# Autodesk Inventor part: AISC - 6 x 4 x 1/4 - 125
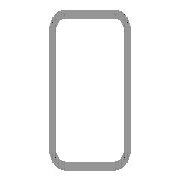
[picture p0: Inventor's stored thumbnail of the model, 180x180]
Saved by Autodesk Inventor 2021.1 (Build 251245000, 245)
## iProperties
Created: 2018-01
Part Number: AISC - 6 x 4 x 1/4 - 125
Material: Steel, Galvanized
Description: Tube
Document SubType Name: Modeling
Standard: AISC
Designer: u1426
Standards Organization: ANSI
Language: en-US
Size Designation: 6 x 4 x 1/4 - 125
Categories: <MemberInstance><Categories><Category DisplayName="Structural Shapes" InternalName="089c4875-fa83-4c05-b084-43b9cc11f5ed" Mnemonic="GRDR"><CategoryParameter Dis
Stock Number: 6 x 4 x 1/4
Density: 7.85 g/cm^3
Appearance: Galvanized
IsCustomPart: 1
G_L: 125.000 in
Author: u1426
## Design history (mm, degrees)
node "Start plane"
sketch "Sketch"
  geometry: L1 (-50.8, -63.5)-(-50.8, 63.5); L2 (-38.1, 76.2)-(38.1, 76.2); L3 (50.8, 63.5)-(50.8, -63.5); L4 (38.1, -76.2)-(-38.1, -76.2); L5 (-38.1, 69.85)-(38.1, 69.85); L6 (44.45, 63.5)-(44.45, -63.5); L7 (38.1, -69.85)-(-38.1, -69.85); L8 (-44.45, -63.5)-(-44.45, 63.5); L9 (0, 110.362)-(0, -110.362) reference; L10 (-74.802, 0)-(74.802, 0) reference; A1 r 12.7 centre (-38.1, -63.5) between (-50.8, -63.5) and (-38.1, -76.2); A2 r 12.7 centre (-38.1, 63.5) between (-38.1, 76.2) and (-50.8, 63.5); A3 r 12.7 centre (38.1, 63.5) between (50.8, 63.5) and (38.1, 76.2); A4 r 12.7 centre (38.1, -63.5) between (38.1, -76.2) and (50.8, -63.5); A5 r 6.35 centre (-38.1, 63.5) between (-38.1, 69.85) and (-44.45, 63.5); A6 r 6.35 centre (38.1, 63.5) between (44.45, 63.5) and (38.1, 69.85); A7 r 6.35 centre (38.1, -63.5) between (38.1, -69.85) and (44.45, -63.5); A8 r 6.35 centre (-38.1, -63.5) between (-44.45, -63.5) and (-38.1, -69.85)
  constraints: 16 end point, 16 point on circle, 8 centre point, 8 tangent, 4 parallel, 3 equal radius, 2 perpendicular, 7 other
  dimensions: "d10" = 152.4 distance between parallel lines of L2 L4 (= G_H); "d11" = 101.6 distance between parallel lines of L1 L3 (= G_W); "d12" = 6.35 distance between parallel lines of L3 L6 (= G_T); "d15" = 76.2 distance between parallel lines of L2 L10 (= 0.5 x d10); "d16" = 50.8 distance between parallel lines of L9 L3 (= 0.5 x d11); "d17" = 12.7 radius of A1 (= G_IR)
extrude "Extrusion2" new body sketch "Sketch" distance "d20" = 498.475; taper "d21" = 0 deg; dims "d22" = 457.2, "d23" = 0
sketch "Sketch5"
  geometry: L1 (88.9, 0)-(88.9, 498.475) reference; L2 (88.9, 498.475)-(38.1, 498.475); L3 (0, 498.475)-(76.2, 498.475) reference; L4 (38.1, 498.475)-(38.1, 203.2); L5 (76.2, 0)-(88.9, 0) reference; L6 (38.1, 203.2)-(88.9, 0); L7 (88.9, 498.475)-(88.9, 0); 1 further point
  constraints: 8 end point, 1 midpoint, 1 perpendicular, 1 vertical
  dimensions: "d26" = 50.8 distance of L1.end L2.end (derived); "d27" = 295.275 distance of L2.end L4.end
extrude "Extrusion3" cut sketch "Sketch5" extent not by distance; stored distance "d28" = 0; taper "d29" = 0 deg
sketch "Sketch6"
  geometry: L1 (38.1, 203.2)-(88.9, 0); L2 (82.355, 0)-(31.75, 202.418); L3 (31.75, 202.418)-(31.75, 498.475); L4 (38.1, 203.2)-(76.2, 50.8) reference; L5 (38.1, 498.475)-(38.1, 203.2) reference; L6 (38.1, 203.2)-(38.1, 498.475); L7 (38.1, 498.475)-(31.75, 498.475); L8 (88.9, 0)-(82.355, 0); L9 (76.2, 0)-(0, 0) reference; 1 further point
  constraints: 12 end point, 1 collinear, 1 perpendicular
  dimensions: "d30" = 6.35 distance between parallel lines of L1 L2
extrude "Extrusion4" join sketch "Sketch6" distance "d31" = 139.7; taper "d32" = 0 deg
body "Solid2"
other parameters: "G_W" = 101.6 [user parameter; used in 1 equation term], "G_H" = 152.4 [user parameter; used in 1 equation term], "G_T" = 6.35 [user parameter; used in 1 equation term], "G_IR" = 12.7 [user parameter; used in 1 equation term], "G_L" = 3175 (= d19) [user parameter], "G_OFFSET_START" = 0 [user parameter; used in 1 equation term], "G_OFFSET_END" = 0 [user parameter], "d13" = 0 (computed from G_OFFSET_START), "B_L" = 3175 [user parameter], "d19" = 3175 (derived)
